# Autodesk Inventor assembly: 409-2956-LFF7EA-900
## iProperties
Created: 2010-09
Part Number: 409-2956-LFF7EA-900
Document SubType Name: Assembly
Designer: S. Boerckel
Mass: 2.80286e+06 g
Surface Area: 775687 cm^2
Volume: 373467 cm^3
Density: 7.50497 g/cm^3
Description: GENERAL ARRANGEMENT
Material: ASSEMBLY
SMR: =<MATERIAL>
Author: S. Boerckel
Revision Number: 0
